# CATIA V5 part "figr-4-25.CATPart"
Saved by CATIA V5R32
Part number: Part1
Bounding box of the stored display mesh (mm): x 0 to 127.525, y -106.271 to 100, z 0 to 100
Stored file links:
  D:\PROJECTS\Project 2022\CATIA V5 6R 2022\Resources\Part Files\c04_catia_v5_6r2022_prt\figr-4-25.CATPart
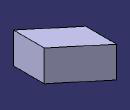
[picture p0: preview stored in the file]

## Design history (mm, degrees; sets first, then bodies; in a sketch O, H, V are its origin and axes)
Body1 (main body)
  Sketch1 on yz-plane, origin (0, 0, 0), H (0, 1, 0), V (0, 0, 1)
    line L1 (0, 0) -> (100, 0)
    line L2 (100, 0) -> (100, 100)
    line L3 (100, 100) -> (0, 100)
    line L4 (0, 100) -> (0, 0)
    horizontal: L1 H, L3 H
    vertical: L2 V, L4 V
  Sketch2 on xy-plane, origin (0, 0, 0), H (1, 0, 0), V (0, 1, 0)
    line L1 (0, 0) -> (60, -50)
  Pad1: profile Sketch1, direction along edge of Sketch2, length 166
